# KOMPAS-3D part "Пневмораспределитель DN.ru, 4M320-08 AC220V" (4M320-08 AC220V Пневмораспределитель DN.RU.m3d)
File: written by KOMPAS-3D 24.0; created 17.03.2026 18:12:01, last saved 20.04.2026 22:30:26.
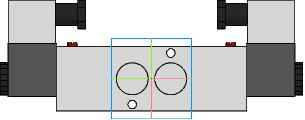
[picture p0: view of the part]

Document properties: Автор: R2D2; Полное имя файла: 4M320-08 AC220V Пневмораспредели тель DN.ru.cdw

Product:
- Part/product: Пневмораспределитель DN.ru  | designation 4M320-08 AC220V
    Масса: 1.2
    Раздел спецификации: Прочие изделия
    Форматы листов документа: A3
    Примечание: D290-00364

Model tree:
1. Операция без истории:1

Expressions: 4M320-08 AC220V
